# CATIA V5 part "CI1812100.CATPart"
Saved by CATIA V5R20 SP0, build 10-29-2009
Part number: CI1812100
Bounding box of the stored display mesh (mm): x -12 to 12, y -9.866 to 118, z -15.524 to 13.481
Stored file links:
  C:\Users\Raffaele\Desktop\3D X SITO CF\BOLEX\19-INCLINED ASSEMBLY REF_CI\CI1812100.CATPart

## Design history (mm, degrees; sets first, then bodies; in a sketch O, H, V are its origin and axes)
Set1
  DatumSurface1 to DatumSurface16 "MANIFOLD_SOLID_BREP #380"
  DatumSurface17 to DatumSurface39 "MANIFOLD_SOLID_BREP #1097"
Body1 (main body)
